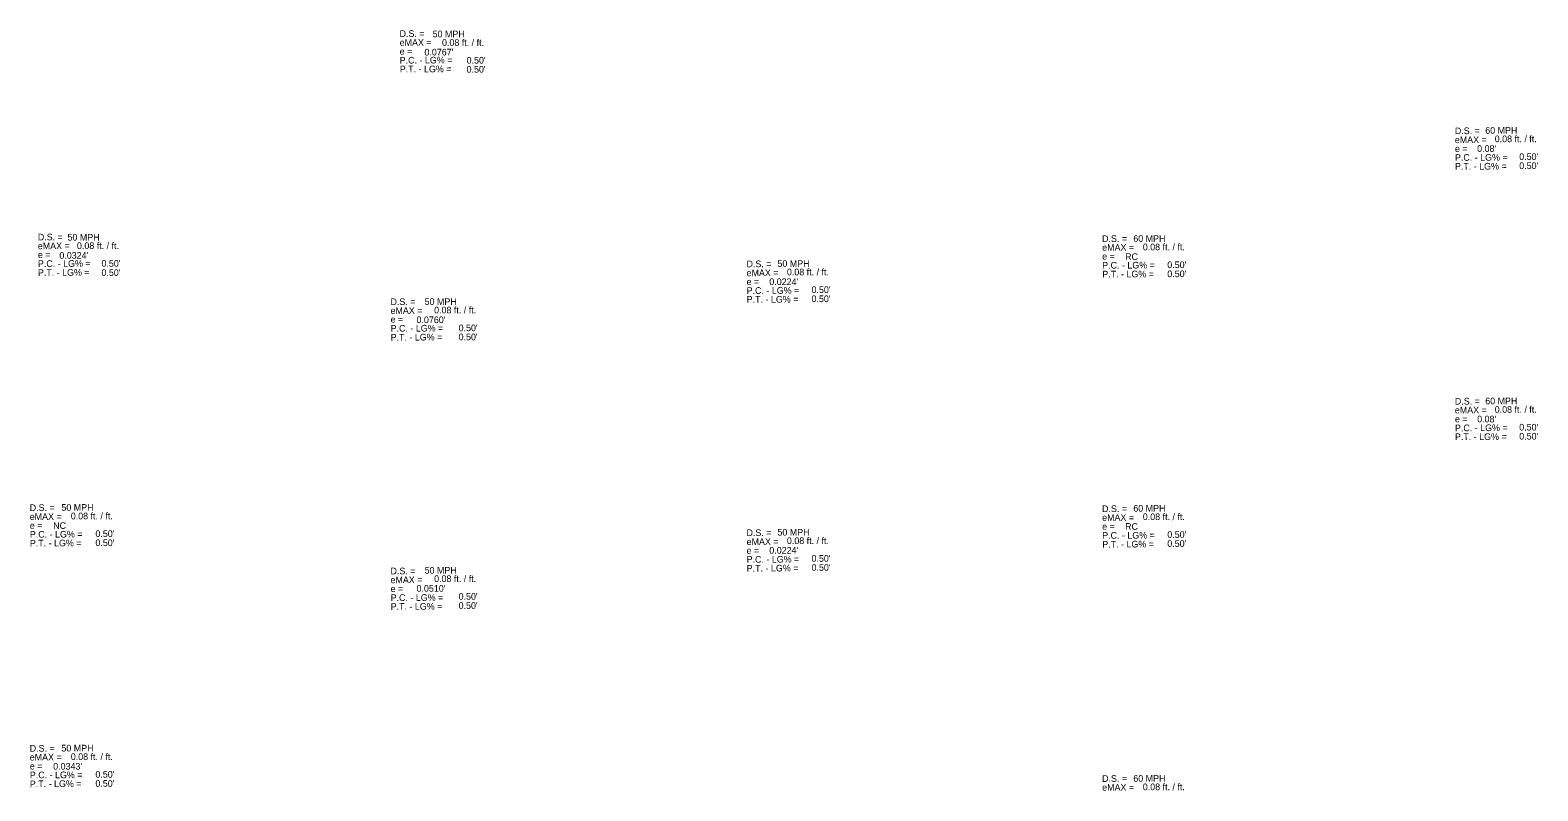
# Model space of a CAD drawing. Extents: x 1609537 to 1612721, y 1094736 to 1096831.
# Drawn here: x 1611307 to 1612721, y 1095472 to 1096186 of the extents above; entities that cross this region are included whole.
import ezdxf

# ---------------------------------------------------------------- set-up
doc = ezdxf.new("R2010")
doc.units = 0
doc.layers.add('RD_HC_Data_50', color=7, linetype='Continuous')

msp = doc.modelspace()

# ---------------------------------------------------------------- texts
at = {"layer": 'RD_HC_Data_50'}
for s, p in [('eMAX = ', (1611653.6, 1096170.9)), ('D.S. = ', (1611653.5, 1096179.3)), ('e = ', (1611653.6, 1096162.6)), ('P.C. - LG% = ', (1611653.6, 1096154.3)), ('P.T. - LG% = ', (1611653.7, 1096146)), ('D.S. = ', (1612643.6, 1096088.1)), ('eMAX = ', (1612643.6, 1096079.7)), ('e = ', (1612643.7, 1096071.4)), ('P.C. - LG% = ', (1612643.7, 1096063.1)), ('P.T. - LG% = ', (1612643.7, 1096054.8)), ('D.S. = ', (1611314.1, 1095988.5)), ('D.S. = ', (1612312.6, 1095987)), ('eMAX = ', (1611314.1, 1095980.2)), ('e = ', (1611314.2, 1095971.9)), ('eMAX = ', (1612312.7, 1095978.7)), ('e = ', (1612312.7, 1095970.4)), ('P.C. - LG% = ', (1611314.2, 1095963.6)), ('P.T. - LG% = ', (1611314.2, 1095955.2)), ('eMAX = ', (1611979.1, 1095954.9)), ('D.S. = ', (1611979, 1095963.3)), ('P.C. - LG% = ', (1612312.7, 1095962)), ('e = ', (1611979.1, 1095946.6)), ('P.T. - LG% = ', (1612312.8, 1095953.7)), ('D.S. = ', (1611645, 1095927.8)), ('P.C. - LG% = ', (1611979.1, 1095938.3)), ('P.T. - LG% = ', (1611979.2, 1095930)), ('eMAX = ', (1611645, 1095919.5)), ('e = ', (1611645.1, 1095911.2)), ('P.C. - LG% = ', (1611645.1, 1095902.9)), ('P.T. - LG% = ', (1611645.1, 1095894.5)), ('D.S. = ', (1612643.6, 1095834.5)), ('eMAX = ', (1612643.6, 1095826.2)), ('e = ', (1612643.7, 1095817.9)), ('P.C. - LG% = ', (1612643.7, 1095809.5)), ('P.T. - LG% = ', (1612643.7, 1095801.2)), ('D.S. = ', (1611306.5, 1095734.7)), ('D.S. = ', (1612312.6, 1095733.7)), ('eMAX = ', (1611306.5, 1095726.3)), ('e = ', (1611306.6, 1095718)), ('eMAX = ', (1612312.7, 1095725.4)), ('e = ', (1612312.7, 1095717.1)), ('P.C. - LG% = ', (1611306.6, 1095709.7)), ('P.T. - LG% = ', (1611306.6, 1095701.4)), ('eMAX = ', (1611979.1, 1095702.8)), ('D.S. = ', (1611979, 1095711.2)), ('P.C. - LG% = ', (1612312.7, 1095708.7)), ('P.T. - LG% = ', (1612312.8, 1095700.4)), ('e = ', (1611979.1, 1095694.5)), ('P.C. - LG% = ', (1611979.1, 1095686.2)), ('D.S. = ', (1611645, 1095675.3)), ('P.T. - LG% = ', (1611979.2, 1095677.9)), ('eMAX = ', (1611645, 1095667)), ('e = ', (1611645.1, 1095658.7)), ('P.C. - LG% = ', (1611645.1, 1095650.3)), ('P.T. - LG% = ', (1611645.1, 1095642)), ('D.S. = ', (1611306.5, 1095509)), ('eMAX = ', (1611306.5, 1095500.7)), ('e = ', (1611306.6, 1095492.3)), ('P.C. - LG% = ', (1611306.6, 1095484)), ('P.T. - LG% = ', (1611306.6, 1095475.7)), ('D.S. = ', (1612312.6, 1095480.7)), ('eMAX = ', (1612312.7, 1095472.4))]:
    msp.add_text(s, height=6.24, rotation=0.2225, dxfattribs=at).set_placement(p)
for s, p in [('50 MPH', (1611684.5, 1096178.9)), ('0.08 ft. / ft.', (1611693.3, 1096170.9)), ("0.0767'", (1611676.8, 1096161.9)), ("0.50'", (1611716.4, 1096154.3)), ("0.50'", (1611716.4, 1096145.8)), ('60 MPH', (1612672.1, 1096088.5)), ("0.08'", (1612664.5, 1096071.5)), ('0.08 ft. / ft.', (1612681, 1096080.6)), ("0.50'", (1612704, 1096063.9)), ("0.50'", (1612704, 1096055.4)), ('50 MPH', (1611341.9, 1095988.3)), ('60 MPH', (1612341.9, 1095987.1)), ("0.0324'", (1611334.3, 1095971.3)), ('0.08 ft. / ft.', (1611350.8, 1095980.4)), ('RC', (1612334.2, 1095970.1)), ('0.08 ft. / ft.', (1612350.8, 1095979.2)), ("0.50'", (1611373.8, 1095963.8)), ("0.50'", (1611373.8, 1095955.2)), ('50 MPH', (1612008, 1095963.6)), ('0.08 ft. / ft.', (1612016.9, 1095955.7)), ("0.50'", (1612373.8, 1095962.5)), ("0.0224'", (1612000.4, 1095946.6)), ("0.50'", (1612373.8, 1095954)), ('50 MPH', (1611677, 1095927.9)), ("0.50'", (1612040, 1095939.1)), ("0.50'", (1612040, 1095930.6)), ('0.08 ft. / ft.', (1611685.9, 1095920)), ("0.0760'", (1611669.4, 1095910.9)), ("0.50'", (1611708.9, 1095903.3)), ("0.50'", (1611708.9, 1095894.8)), ('60 MPH', (1612672.1, 1095834.8)), ("0.08'", (1612664.5, 1095817.8)), ('0.08 ft. / ft.', (1612681, 1095826.8)), ("0.50'", (1612704, 1095810.2)), ("0.50'", (1612704, 1095801.7)), ('50 MPH', (1611336.2, 1095734.9)), ('60 MPH', (1612341.9, 1095734.1)), ('NC', (1611328.5, 1095717.9)), ('0.08 ft. / ft.', (1611345, 1095726.9)), ('RC', (1612334.2, 1095717.1)), ('0.08 ft. / ft.', (1612350.8, 1095726.2)), ("0.50'", (1611368.1, 1095710.3)), ("0.50'", (1611368.1, 1095701.8)), ('50 MPH', (1612008, 1095711.7)), ('0.08 ft. / ft.', (1612016.9, 1095703.7)), ("0.50'", (1612373.8, 1095709.5)), ("0.50'", (1612373.8, 1095701)), ("0.0224'", (1612000.4, 1095694.7)), ("0.50'", (1612040, 1095687.1)), ('50 MPH', (1611677, 1095676)), ("0.50'", (1612040, 1095678.6)), ("0.0510'", (1611669.4, 1095659)), ('0.08 ft. / ft.', (1611685.9, 1095668.1)), ("0.50'", (1611708.9, 1095651.5)), ("0.50'", (1611708.9, 1095642.9)), ('50 MPH', (1611336.2, 1095509.2)), ("0.0343'", (1611328.5, 1095492.2)), ('0.08 ft. / ft.', (1611345, 1095501.2)), ("0.50'", (1611368.1, 1095484.6)), ("0.50'", (1611368.1, 1095476.1)), ('60 MPH', (1612341.9, 1095480.8)), ('0.08 ft. / ft.', (1612350.8, 1095472.9))]:
    msp.add_text(s, height=6.24, dxfattribs=at).set_placement(p)

doc.saveas('drawing.dxf')
